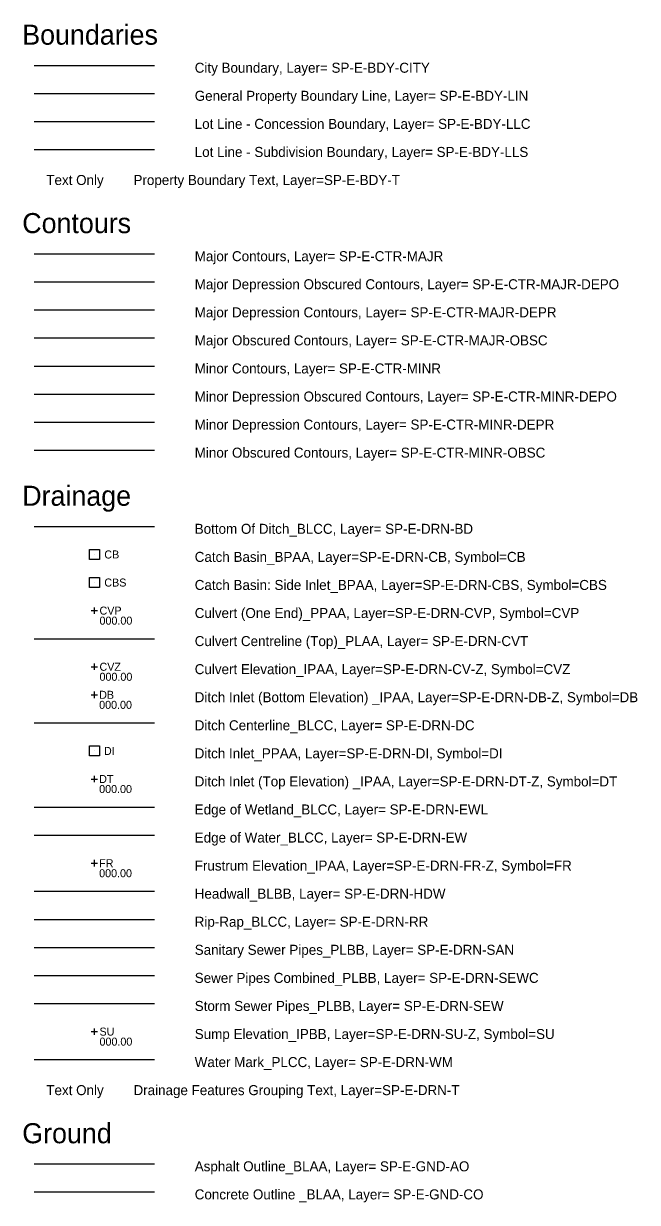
# Model space of a CAD drawing. Extents: x 500528 to 502626, y 4210261 to 4212624.
# Drawn here: x 501383.9 to 501536.9, y 4212030 to 4212324 of the extents above; entities that cross this region are included whole.
import ezdxf

# ---------------------------------------------------------------- set-up
doc = ezdxf.new("R2010")
doc.units = 0
for name, color, linetype in [('Default', 7, 'Continuous'), ('SP-E-BDY-CITY', 7, 'Continuous'), ('SP-E-BDY-LIN', 7, 'Continuous'), ('SP-E-BDY-LLC', 7, 'Continuous'), ('SP-E-BDY-LLS', 7, 'Continuous'), ('SP-E-BDY-T', 7, 'Continuous'), ('SP-E-CTR-MAJR', 7, 'Continuous'), ('SP-E-CTR-MAJR-DEPO', 7, 'Continuous'), ('SP-E-CTR-MAJR-DEPR', 7, 'Continuous'), ('SP-E-CTR-MAJR-OBSC', 7, 'Continuous'), ('SP-E-CTR-MINR', 7, 'Continuous'), ('SP-E-CTR-MINR-DEPO', 7, 'Continuous'), ('SP-E-CTR-MINR-DEPR', 7, 'Continuous'), ('SP-E-CTR-MINR-OBSC', 7, 'Continuous'), ('SP-E-DRN-BD', 7, 'Continuous'), ('SP-E-DRN-CB', 7, 'Continuous'), ('SP-E-DRN-CBS', 7, 'Continuous'), ('SP-E-DRN-CV-Z', 7, 'Continuous'), ('SP-E-DRN-CVP', 7, 'Continuous'), ('SP-E-DRN-CVT', 7, 'Continuous'), ('SP-E-DRN-DB-Z', 7, 'Continuous'), ('SP-E-DRN-DC', 7, 'Continuous'), ('SP-E-DRN-DI', 7, 'Continuous'), ('SP-E-DRN-DT-Z', 7, 'Continuous'), ('SP-E-DRN-EW', 7, 'Continuous'), ('SP-E-DRN-EWL', 7, 'Continuous'), ('SP-E-DRN-FR-Z', 7, 'Continuous'), ('SP-E-DRN-HDW', 7, 'Continuous'), ('SP-E-DRN-RR', 7, 'Continuous'), ('SP-E-DRN-SAN', 7, 'Continuous'), ('SP-E-DRN-SEW', 7, 'Continuous'), ('SP-E-DRN-SEWC', 7, 'Continuous'), ('SP-E-DRN-SU-Z', 7, 'Continuous'), ('SP-E-DRN-T', 7, 'Continuous'), ('SP-E-DRN-WM', 7, 'Continuous'), ('SP-E-GND-AO', 7, 'Continuous'), ('SP-E-GND-CO', 7, 'Continuous')]:
    doc.layers.add(name, color=color, linetype=linetype)

# ---------------------------------------------------------------- blocks, each defined once
blk = doc.blocks.new('POINT_DISPLAY')
at = {"layer": 'Default'}
blk.add_line((0, 0), (0, 0), dxfattribs=at)
blk = doc.blocks.new('CB')
at = {"layer": 'SP-E-DRN-T'}
blk.add_lwpolyline([(-0.125, 0.125), (0.125, 0.125), (0.125, -0.125), (-0.125, -0.125), (-0.125, 0.125)], dxfattribs=at)
at = {"layer": 'SP-E-DRN-CB'}
blk.add_blockref('POINT_DISPLAY', (0, 0), dxfattribs=at)
at = {"layer": 'SP-E-DRN-T'}
blk.add_text('CB', height=0.2, dxfattribs=at).set_placement((0.246, -0.1))
blk = doc.blocks.new('CBS')
at = {"layer": 'SP-E-DRN-T'}
blk.add_lwpolyline([(-0.125, 0.125), (0.125, 0.125), (0.125, -0.125), (-0.125, -0.125), (-0.125, 0.125)], dxfattribs=at)
at = {"layer": 'SP-E-DRN-CBS'}
blk.add_blockref('POINT_DISPLAY', (0, 0), dxfattribs=at)
at = {"layer": 'SP-E-DRN-T'}
blk.add_text('CBS', height=0.2, dxfattribs=at).set_placement((0.246, -0.1))
blk = doc.blocks.new('CVP')
at = {"layer": 'SP-E-DRN-CVP'}
for points in [[(-0.08, 0), (0.08, 0)], [(0, -0.08), (0, 0.08)]]:
    blk.add_lwpolyline(points, dxfattribs=at)
at = {"layer": 'SP-E-DRN-T'}
for s, p in [('CVP', (0.126, -0.1)), ('000.00', (0.126, -0.35))]:
    blk.add_text(s, height=0.2, dxfattribs=at).set_placement(p)
blk = doc.blocks.new('CVZ')
at = {"layer": 'SP-E-DRN-CV-Z'}
for points in [[(-0.08, 0), (0.08, 0)], [(0, -0.08), (0, 0.08)]]:
    blk.add_lwpolyline(points, dxfattribs=at)
at = {"layer": 'SP-E-DRN-T'}
for s, p in [('CVZ', (0.126, -0.1)), ('000.00', (0.126, -0.35))]:
    blk.add_text(s, height=0.2, dxfattribs=at).set_placement(p)
blk = doc.blocks.new('DB')
at = {"layer": 'SP-E-DRN-DB-Z'}
for points in [[(-0.08, 0), (0.08, 0)], [(0, -0.08), (0, 0.08)]]:
    blk.add_lwpolyline(points, dxfattribs=at)
at = {"layer": 'SP-E-DRN-T'}
for s, p in [('DB', (0.117, -0.1)), ('000.00', (0.117, -0.35))]:
    blk.add_text(s, height=0.2, dxfattribs=at).set_placement(p)
blk = doc.blocks.new('DI')
at = {"layer": 'SP-E-DRN-DI'}
for points in [[(-0.125, 0.125), (0.125, 0.125), (0.125, -0.125), (-0.125, -0.125), (-0.125, 0.125)], [(0, 0), (0, 0)]]:
    blk.add_lwpolyline(points, dxfattribs=at)
at = {"layer": 'SP-E-DRN-T'}
blk.add_text('DI', height=0.2, dxfattribs=at).set_placement((0.237, -0.1))
blk = doc.blocks.new('DT')
at = {"layer": 'SP-E-DRN-DT-Z'}
for points in [[(-0.08, 0), (0.08, 0)], [(0, -0.08), (0, 0.08)]]:
    blk.add_lwpolyline(points, dxfattribs=at)
at = {"layer": 'SP-E-DRN-T'}
for s, p in [('DT', (0.117, -0.1)), ('000.00', (0.117, -0.35))]:
    blk.add_text(s, height=0.2, dxfattribs=at).set_placement(p)
blk = doc.blocks.new('FR')
at = {"layer": 'SP-E-DRN-FR-Z'}
for points in [[(-0.08, 0), (0.08, 0)], [(0, -0.08), (0, 0.08)]]:
    blk.add_lwpolyline(points, dxfattribs=at)
at = {"layer": 'SP-E-DRN-T'}
for s, p in [('FR', (0.117, -0.1)), ('000.00', (0.117, -0.35))]:
    blk.add_text(s, height=0.2, dxfattribs=at).set_placement(p)
blk = doc.blocks.new('SU')
at = {"layer": 'SP-E-DRN-SU-Z'}
for points in [[(-0.08, 0), (0.08, 0)], [(0, -0.08), (0, 0.08)]]:
    blk.add_lwpolyline(points, dxfattribs=at)
at = {"layer": 'SP-E-DRN-T'}
for s, p in [('SU', (0.126, -0.1)), ('000.00', (0.126, -0.35))]:
    blk.add_text(s, height=0.2, dxfattribs=at).set_placement(p)

msp = doc.modelspace()

# ---------------------------------------------------------------- linework, layer by layer
at = {"layer": 'SP-E-BDY-CITY'}
msp.add_line((501386.55, 4212313.59), (501416.55, 4212313.59), dxfattribs=at)
at = {"layer": 'SP-E-BDY-LIN'}
msp.add_line((501386.55, 4212306.59), (501416.55, 4212306.59), dxfattribs=at)
at = {"layer": 'SP-E-BDY-LLC'}
msp.add_line((501386.55, 4212299.59), (501416.55, 4212299.59), dxfattribs=at)
at = {"layer": 'SP-E-BDY-LLS'}
msp.add_line((501386.55, 4212292.59), (501416.55, 4212292.59), dxfattribs=at)
at = {"layer": 'SP-E-CTR-MAJR'}
msp.add_line((501386.55, 4212266.59), (501416.55, 4212266.59), dxfattribs=at)
at = {"layer": 'SP-E-CTR-MAJR-DEPO'}
msp.add_line((501386.55, 4212259.59), (501416.55, 4212259.59), dxfattribs=at)
at = {"layer": 'SP-E-CTR-MAJR-DEPR'}
msp.add_line((501386.55, 4212252.59), (501416.55, 4212252.59), dxfattribs=at)
at = {"layer": 'SP-E-CTR-MAJR-OBSC'}
msp.add_line((501386.55, 4212245.59), (501416.55, 4212245.59), dxfattribs=at)
at = {"layer": 'SP-E-CTR-MINR'}
msp.add_line((501386.55, 4212238.59), (501416.55, 4212238.59), dxfattribs=at)
at = {"layer": 'SP-E-CTR-MINR-DEPO'}
msp.add_line((501386.55, 4212231.59), (501416.55, 4212231.59), dxfattribs=at)
at = {"layer": 'SP-E-CTR-MINR-DEPR'}
msp.add_line((501386.55, 4212224.59), (501416.55, 4212224.59), dxfattribs=at)
at = {"layer": 'SP-E-CTR-MINR-OBSC'}
msp.add_line((501386.55, 4212217.59), (501416.55, 4212217.59), dxfattribs=at)
at = {"layer": 'SP-E-DRN-BD'}
msp.add_line((501386.55, 4212198.59), (501416.55, 4212198.59), dxfattribs=at)
at = {"layer": 'SP-E-DRN-CVT'}
msp.add_line((501386.55, 4212170.59), (501416.55, 4212170.59), dxfattribs=at)
at = {"layer": 'SP-E-DRN-DC'}
msp.add_line((501386.55, 4212149.59), (501416.55, 4212149.59), dxfattribs=at)
at = {"layer": 'SP-E-DRN-EW'}
msp.add_line((501386.55, 4212121.59), (501416.55, 4212121.59), dxfattribs=at)
at = {"layer": 'SP-E-DRN-EWL'}
msp.add_line((501386.55, 4212128.59), (501416.55, 4212128.59), dxfattribs=at)
at = {"layer": 'SP-E-DRN-HDW'}
msp.add_line((501386.55, 4212107.59), (501416.55, 4212107.59), dxfattribs=at)
at = {"layer": 'SP-E-DRN-RR'}
msp.add_line((501386.55, 4212100.59), (501416.55, 4212100.59), dxfattribs=at)
at = {"layer": 'SP-E-DRN-SAN'}
msp.add_line((501386.55, 4212093.59), (501416.55, 4212093.59), dxfattribs=at)
at = {"layer": 'SP-E-DRN-SEW'}
msp.add_line((501386.55, 4212079.59), (501416.55, 4212079.59), dxfattribs=at)
at = {"layer": 'SP-E-DRN-SEWC'}
msp.add_line((501386.55, 4212086.59), (501416.55, 4212086.59), dxfattribs=at)
at = {"layer": 'SP-E-DRN-WM'}
msp.add_line((501386.55, 4212065.59), (501416.55, 4212065.59), dxfattribs=at)
at = {"layer": 'SP-E-GND-AO'}
msp.add_line((501386.55, 4212039.59), (501416.55, 4212039.59), dxfattribs=at)
at = {"layer": 'SP-E-GND-CO'}
msp.add_line((501386.55, 4212032.59), (501416.55, 4212032.59), dxfattribs=at)

# ---------------------------------------------------------------- block references
at = {"layer": 'SP-E-DRN-CB', "xscale": 10, "yscale": 10}
msp.add_blockref('CB', (501401.55, 4212191.59), dxfattribs=at)
at = {"layer": 'SP-E-DRN-CBS', "xscale": 10, "yscale": 10}
msp.add_blockref('CBS', (501401.55, 4212184.59), dxfattribs=at)
at = {"layer": 'SP-E-DRN-CV-Z', "xscale": 10, "yscale": 10}
msp.add_blockref('CVZ', (501401.55, 4212163.59), dxfattribs=at)
at = {"layer": 'SP-E-DRN-CVP', "xscale": 10, "yscale": 10}
msp.add_blockref('CVP', (501401.55, 4212177.59), dxfattribs=at)
at = {"layer": 'SP-E-DRN-DB-Z', "xscale": 10, "yscale": 10}
msp.add_blockref('DB', (501401.55, 4212156.59), dxfattribs=at)
at = {"layer": 'SP-E-DRN-DI', "xscale": 10, "yscale": 10}
msp.add_blockref('DI', (501401.55, 4212142.59), dxfattribs=at)
at = {"layer": 'SP-E-DRN-DT-Z', "xscale": 10, "yscale": 10}
msp.add_blockref('DT', (501401.55, 4212135.59), dxfattribs=at)
at = {"layer": 'SP-E-DRN-FR-Z', "xscale": 10, "yscale": 10}
msp.add_blockref('FR', (501401.55, 4212114.59), dxfattribs=at)
at = {"layer": 'SP-E-DRN-SU-Z', "xscale": 10, "yscale": 10}
msp.add_blockref('SU', (501401.55, 4212072.59), dxfattribs=at)

# ---------------------------------------------------------------- texts
at = {"layer": 'Default'}
for s, p in [('Boundaries ', (501383.55, 4212318.74)), ('Contours ', (501383.55, 4212271.74)), ('Drainage ', (501383.55, 4212203.74)), ('Ground ', (501383.55, 4212044.74))]:
    msp.add_text(s, height=5, dxfattribs=at).set_placement(p)
at = {"layer": 'SP-E-BDY-CITY'}
msp.add_text('City Boundary, Layer= SP-E-BDY-CITY ', height=2.5, dxfattribs=at).set_placement((501426.55, 4212311.74))
at = {"layer": 'SP-E-BDY-LIN'}
msp.add_text('General Property Boundary Line, Layer= SP-E-BDY-LIN ', height=2.5, dxfattribs=at).set_placement((501426.55, 4212304.74))
at = {"layer": 'SP-E-BDY-LLC'}
msp.add_text('Lot Line - Concession Boundary, Layer= SP-E-BDY-LLC ', height=2.5, dxfattribs=at).set_placement((501426.55, 4212297.74))
at = {"layer": 'SP-E-BDY-LLS'}
msp.add_text('Lot Line - Subdivision Boundary, Layer= SP-E-BDY-LLS ', height=2.5, dxfattribs=at).set_placement((501426.55, 4212290.74))
at = {"layer": 'SP-E-BDY-T'}
msp.add_text('Text Only        Property Boundary Text, Layer=SP-E-BDY-T', height=2.5, dxfattribs=at).set_placement((501389.55, 4212283.74))
at = {"layer": 'SP-E-CTR-MAJR'}
msp.add_text('Major Contours, Layer= SP-E-CTR-MAJR ', height=2.5, dxfattribs=at).set_placement((501426.55, 4212264.74))
at = {"layer": 'SP-E-CTR-MAJR-DEPO'}
msp.add_text('Major Depression Obscured Contours, Layer= SP-E-CTR-MAJR-DEPO ', height=2.5, dxfattribs=at).set_placement((501426.55, 4212257.74))
at = {"layer": 'SP-E-CTR-MAJR-DEPR'}
msp.add_text('Major Depression Contours, Layer= SP-E-CTR-MAJR-DEPR ', height=2.5, dxfattribs=at).set_placement((501426.55, 4212250.74))
at = {"layer": 'SP-E-CTR-MAJR-OBSC'}
msp.add_text('Major Obscured Contours, Layer= SP-E-CTR-MAJR-OBSC ', height=2.5, dxfattribs=at).set_placement((501426.55, 4212243.74))
at = {"layer": 'SP-E-CTR-MINR'}
msp.add_text('Minor Contours, Layer= SP-E-CTR-MINR ', height=2.5, dxfattribs=at).set_placement((501426.55, 4212236.74))
at = {"layer": 'SP-E-CTR-MINR-DEPO'}
msp.add_text('Minor Depression Obscured Contours, Layer= SP-E-CTR-MINR-DEPO ', height=2.5, dxfattribs=at).set_placement((501426.55, 4212229.74))
at = {"layer": 'SP-E-CTR-MINR-DEPR'}
msp.add_text('Minor Depression Contours, Layer= SP-E-CTR-MINR-DEPR ', height=2.5, dxfattribs=at).set_placement((501426.55, 4212222.74))
at = {"layer": 'SP-E-CTR-MINR-OBSC'}
msp.add_text('Minor Obscured Contours, Layer= SP-E-CTR-MINR-OBSC ', height=2.5, dxfattribs=at).set_placement((501426.55, 4212215.74))
at = {"layer": 'SP-E-DRN-BD'}
msp.add_text('Bottom Of Ditch_BLCC, Layer= SP-E-DRN-BD ', height=2.5, dxfattribs=at).set_placement((501426.55, 4212196.74))
at = {"layer": 'SP-E-DRN-CB'}
msp.add_text('Catch Basin_BPAA, Layer=SP-E-DRN-CB, Symbol=CB ', height=2.5, dxfattribs=at).set_placement((501426.55, 4212189.74))
at = {"layer": 'SP-E-DRN-CBS'}
msp.add_text('Catch Basin: Side Inlet_BPAA, Layer=SP-E-DRN-CBS, Symbol=CBS ', height=2.5, dxfattribs=at).set_placement((501426.55, 4212182.74))
at = {"layer": 'SP-E-DRN-CV-Z'}
msp.add_text('Culvert Elevation_IPAA, Layer=SP-E-DRN-CV-Z, Symbol=CVZ ', height=2.5, dxfattribs=at).set_placement((501426.55, 4212161.74))
at = {"layer": 'SP-E-DRN-CVP'}
msp.add_text('Culvert (One End)_PPAA, Layer=SP-E-DRN-CVP, Symbol=CVP ', height=2.5, dxfattribs=at).set_placement((501426.55, 4212175.74))
at = {"layer": 'SP-E-DRN-CVT'}
msp.add_text('Culvert Centreline (Top)_PLAA, Layer= SP-E-DRN-CVT ', height=2.5, dxfattribs=at).set_placement((501426.55, 4212168.74))
at = {"layer": 'SP-E-DRN-DB-Z'}
msp.add_text('Ditch Inlet (Bottom Elevation) _IPAA, Layer=SP-E-DRN-DB-Z, Symbol=DB ', height=2.5, dxfattribs=at).set_placement((501426.55, 4212154.74))
at = {"layer": 'SP-E-DRN-DC'}
msp.add_text('Ditch Centerline_BLCC, Layer= SP-E-DRN-DC ', height=2.5, dxfattribs=at).set_placement((501426.55, 4212147.74))
at = {"layer": 'SP-E-DRN-DI'}
msp.add_text('Ditch Inlet_PPAA, Layer=SP-E-DRN-DI, Symbol=DI ', height=2.5, dxfattribs=at).set_placement((501426.55, 4212140.74))
at = {"layer": 'SP-E-DRN-DT-Z'}
msp.add_text('Ditch Inlet (Top Elevation) _IPAA, Layer=SP-E-DRN-DT-Z, Symbol=DT ', height=2.5, dxfattribs=at).set_placement((501426.55, 4212133.74))
at = {"layer": 'SP-E-DRN-EW'}
msp.add_text('Edge of Water_BLCC, Layer= SP-E-DRN-EW ', height=2.5, dxfattribs=at).set_placement((501426.55, 4212119.74))
at = {"layer": 'SP-E-DRN-EWL'}
msp.add_text('Edge of Wetland_BLCC, Layer= SP-E-DRN-EWL ', height=2.5, dxfattribs=at).set_placement((501426.55, 4212126.74))
at = {"layer": 'SP-E-DRN-FR-Z'}
msp.add_text('Frustrum Elevation_IPAA, Layer=SP-E-DRN-FR-Z, Symbol=FR ', height=2.5, dxfattribs=at).set_placement((501426.55, 4212112.74))
at = {"layer": 'SP-E-DRN-HDW'}
msp.add_text('Headwall_BLBB, Layer= SP-E-DRN-HDW ', height=2.5, dxfattribs=at).set_placement((501426.55, 4212105.74))
at = {"layer": 'SP-E-DRN-RR'}
msp.add_text('Rip-Rap_BLCC, Layer= SP-E-DRN-RR ', height=2.5, dxfattribs=at).set_placement((501426.55, 4212098.74))
at = {"layer": 'SP-E-DRN-SAN'}
msp.add_text('Sanitary Sewer Pipes_PLBB, Layer= SP-E-DRN-SAN ', height=2.5, dxfattribs=at).set_placement((501426.55, 4212091.74))
at = {"layer": 'SP-E-DRN-SEW'}
msp.add_text('Storm Sewer Pipes_PLBB, Layer= SP-E-DRN-SEW ', height=2.5, dxfattribs=at).set_placement((501426.55, 4212077.74))
at = {"layer": 'SP-E-DRN-SEWC'}
msp.add_text('Sewer Pipes Combined_PLBB, Layer= SP-E-DRN-SEWC ', height=2.5, dxfattribs=at).set_placement((501426.55, 4212084.74))
at = {"layer": 'SP-E-DRN-SU-Z'}
msp.add_text('Sump Elevation_IPBB, Layer=SP-E-DRN-SU-Z, Symbol=SU ', height=2.5, dxfattribs=at).set_placement((501426.55, 4212070.74))
at = {"layer": 'SP-E-DRN-T'}
msp.add_text('Text Only        Drainage Features Grouping Text, Layer=SP-E-DRN-T', height=2.5, dxfattribs=at).set_placement((501389.55, 4212056.74))
at = {"layer": 'SP-E-DRN-WM'}
msp.add_text('Water Mark_PLCC, Layer= SP-E-DRN-WM ', height=2.5, dxfattribs=at).set_placement((501426.55, 4212063.74))
at = {"layer": 'SP-E-GND-AO'}
msp.add_text('Asphalt Outline_BLAA, Layer= SP-E-GND-AO ', height=2.5, dxfattribs=at).set_placement((501426.55, 4212037.74))
at = {"layer": 'SP-E-GND-CO'}
msp.add_text('Concrete Outline _BLAA, Layer= SP-E-GND-CO ', height=2.5, dxfattribs=at).set_placement((501426.55, 4212030.74))

doc.saveas('drawing.dxf')
